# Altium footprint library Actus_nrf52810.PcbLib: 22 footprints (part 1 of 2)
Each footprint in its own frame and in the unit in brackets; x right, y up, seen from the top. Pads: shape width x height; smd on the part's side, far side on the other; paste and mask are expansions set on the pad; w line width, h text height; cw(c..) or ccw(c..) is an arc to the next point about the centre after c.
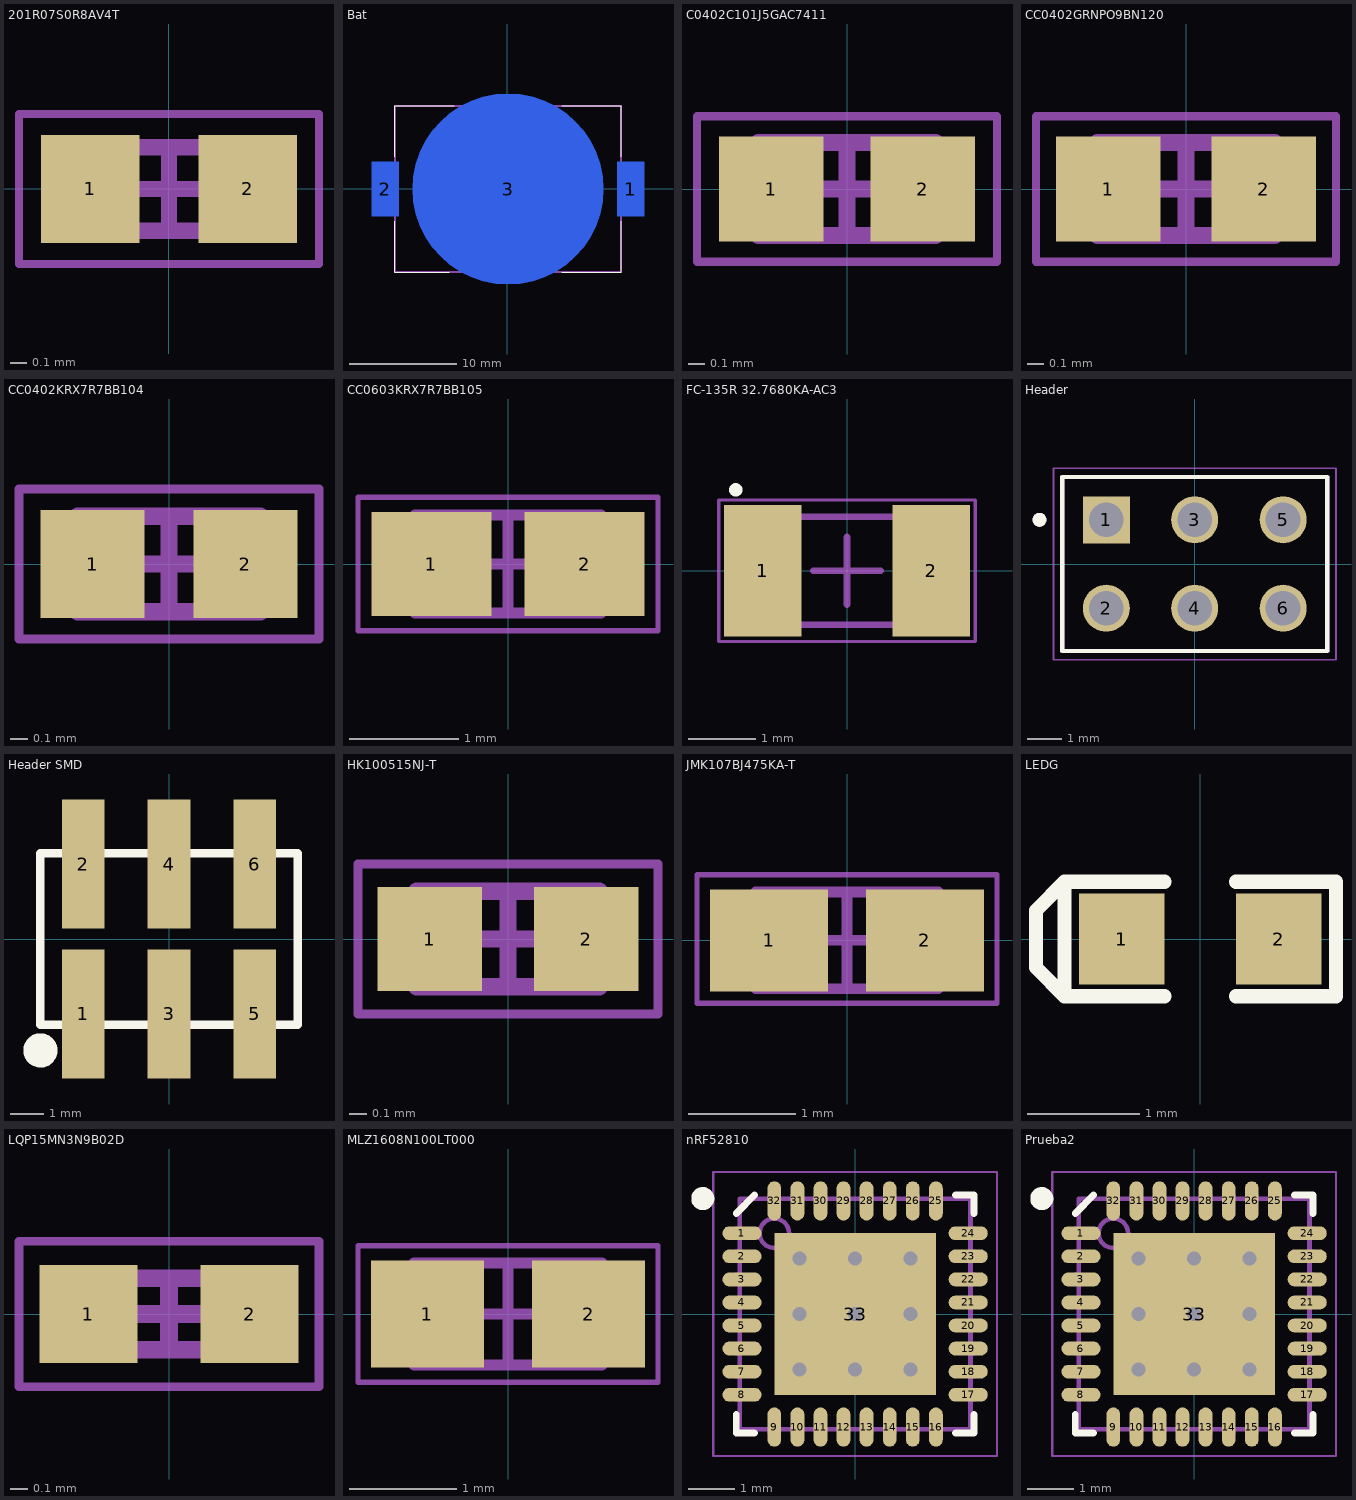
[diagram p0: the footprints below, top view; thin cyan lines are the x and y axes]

## 201R07S0R8AV4T [mm] "C3, 0.8pF, 0402, Johanson Dielectrics (Dimensiones no especificadas en datasheet, medidas tomadas de Mouser)"
height 0.64
pads (2):
  rect 0.6x0.66 smd: 1(-0.48,0) 2(0.48,0)
Mechanical 13:
  lines w0.1: -0.51,-0.255 0.51,-0.255 0.51,0.255 -0.51,0.255 -0.51,-0.255
Mechanical 15:
  lines w0.05: -0.914,-0.457 0.914,-0.457 0.914,0.457 -0.914,0.457 -0.914,-0.457
  lines w0.1: -0.255,0 0.255,0 ; 0,-0.255 0,0.255
3D body: height 0.64, standoff 0, extent 0.26,-0.255 0.51,0.255
3D body: height 0.64, standoff 0, extent -0.51,-0.255 -0.26,0.255
3D body: height 0.64, standoff 0, extent -0.26,-0.255 0.26,0.255

## Bat [mm]
pads (3):
  rect 2.5x5.1 smd far side: 1(11.501,-0.025) 2(-11.399,-0.025)
  round 17.8 smd far side mask+0.102: 3(0.051,-0.025)
Top Overlay:
  lines w0.1: -10.499,-3.025 -10.499,-7.775 -5.449,-7.775 ; -10.499,2.975 -10.499,7.725 -4.949,7.725 ; 5.051,-7.775 10.601,-7.775 10.601,-3.025 ; 5.051,7.725 10.601,7.725 10.601,2.975
Mechanical 13:
  lines w0.2: -10.499,-7.775 10.601,-7.775 10.601,7.725 -10.499,7.725 -10.499,-7.775
3D body "Coin Retainer.STEP": height 4.08, standoff 0.01, extent -11.519,-7.792 11.722,8.687
3D body: height 0.35, standoff -16.13, extent 2.794,-9.017 2.794,-9.017
3D body: height 2.9, standoff -2.9, extent 0.051,-0.025 0.051,-0.025

## C0402C101J5GAC7411 [mm] "C7: 100 pF, 0402, KEMET"
height 0.55
pads (2):
  rect 0.62x0.62 smd: 1(-0.45,0) 2(0.45,0)
Mechanical 13:
  lines w0.1: -0.525,-0.275 -0.525,0.275 0.525,0.275 0.525,-0.275 -0.525,-0.275
Mechanical 15:
  lines w0.05: -0.889,-0.432 -0.889,0.432 0.889,0.432 0.889,-0.432 -0.889,-0.432
  lines w0.1: -0.275,0 0.275,0 ; 0,-0.275 0,0.275
3D body: height 0.55, standoff 0, extent -0.225,-0.275 0.225,0.275
3D body: height 0.55, standoff 0, extent -0.525,-0.275 -0.225,0.275
3D body: height 0.55, standoff 0, extent 0.225,-0.275 0.525,0.275

## CC0402GRNPO9BN120 [mm] "C1, C2, C11, C12: 12pF, 0402, Yageo"
height 0.55
pads (2):
  rect 0.62x0.62 smd: 1(-0.46,0) 2(0.46,0)
Mechanical 13:
  lines w0.1: -0.525,-0.275 0.525,-0.275 0.525,0.275 -0.525,0.275 -0.525,-0.275
Mechanical 15:
  lines w0.05: -0.889,-0.432 -0.889,-0.229 -0.889,0.229 -0.889,0.432 0.889,0.432 0.889,-0.432 -0.889,-0.432
  lines w0.1: -0.275,0 0.275,0 ; 0,-0.275 0,0.275
3D body: height 0.55, standoff 0, extent 0.275,-0.275 0.525,0.275
3D body: height 0.55, standoff 0, extent -0.525,-0.275 -0.275,0.275
3D body: height 0.55, standoff 0, extent -0.275,-0.275 0.275,0.275

## CC0402KRX7R7BB104 [mm] "C4, C5, C8: 100nF (0.1uF), 0402, Yageo"
height 0.55
pads (2):
  rect 0.6x0.62 smd: 1(-0.44,0) 2(0.44,0)
Mechanical 13:
  lines w0.1: -0.525,-0.275 -0.525,0.275 0.525,0.275 0.525,-0.275 -0.525,-0.275
Mechanical 15:
  lines w0.05: -0.864,-0.432 -0.864,0.432 0.864,0.432 0.864,-0.432 -0.864,-0.432
  lines w0.1: -0.275,0 0.275,0 ; 0,-0.275 0,0.275
3D body: height 0.55, standoff 0, extent -0.275,-0.275 0.275,0.275
3D body: height 0.55, standoff 0, extent -0.525,-0.275 -0.275,0.275
3D body: height 0.55, standoff 0, extent 0.275,-0.275 0.525,0.275

## CC0603KRX7R7BB105 [mm] "C10: 1.0uF, 0603, Yageo"
height 0.9
pads (2):
  rect 1.1x0.95 smd: 1(-0.7,0) 2(0.7,0)
Mechanical 13:
  lines w0.1: -0.85,-0.45 -0.85,0.45 0.85,0.45 0.85,-0.45 -0.85,-0.45
Mechanical 15:
  lines w0.05: -1.372,-0.61 -1.372,0.61 1.372,0.61 1.372,-0.61 -1.372,-0.61
  lines w0.1: -0.45,0 0.45,0 ; 0,-0.45 0,0.45
3D body: height 0.9, standoff 0, extent -0.45,-0.45 0.45,0.45
3D body: height 0.9, standoff 0, extent -0.85,-0.45 -0.45,0.45
3D body: height 0.9, standoff 0, extent 0.45,-0.45 0.85,0.45

## FC-135R 32.7680KA-AC3 [mm] "X2: 32.7680KHZ, XTAL_3215, EPSON"
height 0.9
pads (2):
  rect 1.15x1.95 smd: 1(-1.25,0) 2(1.25,0)
Top Overlay:
  circle w0.1: c-1.65,1.2 r0.05
Mechanical 13:
  lines w0.1: -1.65,-0.8 1.65,-0.8 1.65,0.8 -1.65,0.8 -1.65,-0.8
Mechanical 15:
  lines w0.05: -1.9,-1.05 1.9,-1.05 1.9,1.05 -1.9,1.05 -1.9,-1.05
  lines w0.1: -0.5,0 0.5,0 ; 0,-0.5 0,0.5
3D body: height 0.9, standoff 0, extent -1.65,-0.8 1.65,0.8

## Header [mm]
pads (6):
  rect 1.35x1.35 hole 1: 1(-2.54,1.27)
  round 1.35 hole 1: 2(-2.54,-1.27) 3(0,1.27) 4(0,-1.27) 5(2.54,1.27) 6(2.54,-1.27)
Top Overlay:
  circle w0.2: c-4.46,1.27 r0.1
  lines w0.127: -3.81,-2.5 -3.81,2.5 3.81,2.5 3.81,-2.5 -3.81,-2.5
Mechanical 4:
  circle w0.2: c-4.46,1.27 r0.1
  circle w0.2: c-4.46,1.27 r0.1
  lines w0.127: -3.81,-2.5 -3.81,2.5 ; -3.81,-2.5 3.81,-2.5 ; -3.81,-2.5 3.81,-2.5 ; -3.81,-2.5 -3.81,2.5 ; -3.81,-2.5 3.81,-2.5 ; -3.81,-2.5 3.81,-2.5 ; -3.81,2.5 3.81,2.5 ; -3.81,2.5 3.81,2.5 ; 3.81,-2.5 3.81,2.5 ; 3.81,-2.5 3.81,2.5
Mechanical 16:
  lines w0.05: -4.06,-2.75 -4.06,2.75 4.06,2.75 4.06,-2.75 -4.06,-2.75
3D body: height 0.35, standoff -16.13, extent 2.54,1.27 2.54,1.27
3D body "CON6_2X3_P100UM_HDR.step": height 9.5, standoff -5.08, extent -3.81,-2.54 3.81,2.54

## Header SMD [mil]
pads (6):
  rect 50x150 smd: 1(-100,-87.5) 2(-100,87.5) 3(0,-87.5) 4(0,87.5) 5(100,-87.5) 6(100,87.5)
Top Overlay:
  circle w20: c-150,-130 r10
  lines w10: -150,-100 -150,100 150,100 150,-100 -150,-100
3D body "pin_header_a-sl254-dg-g06mp1.stp": height 382.03, standoff -1.57, extent -149.99,-147.63 150.01,147.64

## HK100515NJ-T [mm] "L3: 15nH, 0402, Taiyo Yuden"
height 0.55
pads (2):
  rect 0.6x0.6 smd: 1(-0.45,0) 2(0.45,0)
Mechanical 13:
  lines w0.1: -0.525,-0.275 0.525,-0.275 0.525,0.275 -0.525,0.275 -0.525,-0.275
Mechanical 15:
  lines w0.05: -0.864,-0.432 0.864,-0.432 0.864,0.432 -0.864,0.432 -0.864,-0.432
  lines w0.1: -0.275,0 0.275,0 ; 0,-0.275 0,0.275
3D body: height 0.55, standoff 0, extent 0.275,-0.275 0.525,0.275
3D body: height 0.55, standoff 0, extent -0.525,-0.275 -0.275,0.275
3D body: height 0.55, standoff 0, extent -0.275,-0.275 0.275,0.275

## JMK107BJ475KA-T [mm] "C9: 4.7uF, 0603, Taiyo Yuden"
height 0.9
pads (2):
  rect 1.1x0.95 smd: 1(-0.725,0) 2(0.725,0)
Mechanical 13:
  lines w0.1: -0.85,-0.45 0.85,-0.45 0.85,0.45 -0.85,0.45 -0.85,-0.45
Mechanical 15:
  lines w0.05: -1.397,-0.584 1.397,-0.584 1.397,0.61 -1.397,0.61 -1.397,-0.584
  lines w0.1: -0.45,0 0.45,0 ; 0,-0.45 0,0.45
3D body: height 0.9, standoff 0, extent 0.37,-0.45 0.85,0.45
3D body: height 0.9, standoff 0, extent -0.85,-0.45 -0.37,0.45
3D body: height 0.9, standoff 0, extent -0.37,-0.45 0.37,0.45

## LEDG [mil]
pads (2):
  rect 30x32 smd: 1(-27.5,0) 2(27.5,0)
Top Overlay:
  lines w5: -12.5,-20 -47.5,-20 ; -12.5,20 -47.5,20 ; 12.5,-20 47.5,-20 47.5,20 12.5,20 ; -47.5,-20 -57.5,-10 -57.5,10 -47.5,20 ; -47.5,-20 -47.5,20
3D body "User Library-led_0603_green.step": height 23.62, standoff 0, extent -31.63,-15.75 32.15,15.75

## LQP15MN3N9B02D [mm] "L1: 3.9 nH, 0402 (1005 metric), Murata Electronics"
height 0.45
pads (2):
  rect 0.55x0.55 smd: 1(-0.45,0) 2(0.45,0)
Mechanical 13:
  lines w0.1: -0.55,-0.2 -0.55,0.2 0.55,0.2 0.55,-0.2 -0.55,-0.2
Mechanical 15:
  lines w0.05: -0.838,-0.406 0.838,-0.406 0.838,0.406 0.483,0.406 -0.437,0.406 -0.838,0.406 -0.838,-0.406
  lines w0.1: -0.2,0 0.2,0 ; 0,-0.2 0,0.2
3D body: height 0.45, standoff 0, extent -0.3,-0.2 0.3,0.2
3D body: height 0.45, standoff 0, extent -0.55,-0.2 -0.3,0.2
3D body: height 0.45, standoff 0, extent 0.3,-0.2 0.55,0.2

## MLZ1608N100LT000 [mm] "L2: 10 uH, 0603 (1608 metric), TDK"
height 0.95
pads (2):
  rect 1.05x1 smd: 1(-0.75,0) 2(0.75,0)
Mechanical 13:
  lines w0.1: -0.875,-0.475 0.875,-0.475 0.875,0.475 -0.875,0.475 -0.875,-0.475
Mechanical 15:
  lines w0.05: -1.397,-0.635 1.397,-0.635 1.397,0.635 0.75,0.635 -0.75,0.635 -1.397,0.635 -1.397,-0.635
  lines w0.1: -0.475,0 0.475,0 ; 0,-0.475 0,0.475
3D body: height 0.95, standoff 0, extent 0.575,-0.475 0.875,0.475
3D body: height 0.95, standoff 0, extent -0.875,-0.475 -0.575,0.475
3D body: height 0.95, standoff 0, extent -0.575,-0.475 0.575,0.475

## nRF52810 [mm] "QFN, 32-Leads, Body 5.00x5.00mm, Pitch 0.50mm, Thermal Pad 3.50x3.50mm, IPC Medium Density"
height 0.9
pads (33):
  oval 0.85x0.3 smd mask+0.076: 1(-2.45,1.75) 2(-2.45,1.25) 3(-2.45,0.75) 4(-2.45,0.25) 5(-2.45,-0.25) 6(-2.45,-0.75) 7(-2.45,-1.25) 8(-2.45,-1.75) 17(2.45,-1.75) 18(2.45,-1.25) 19(2.45,-0.75) 20(2.45,-0.25) 21(2.45,0.25) 22(2.45,0.75) 23(2.45,1.25) 24(2.45,1.75)
  oval 0.3x0.85 smd mask+0.076: 9(-1.75,-2.45) 10(-1.25,-2.45) 11(-0.75,-2.45) 12(-0.25,-2.45) 13(0.25,-2.45) 14(0.75,-2.45) 15(1.25,-2.45) 16(1.75,-2.45) 25(1.75,2.45) 26(1.25,2.45) 27(0.75,2.45) 28(0.25,2.45) 29(-0.25,2.45) 30(-0.75,2.45) 31(-1.25,2.45) 32(-1.75,2.45)
  rect 3.5x3.5 smd: 33(0,0)
via 0,0 diameter 0.61 hole 0.305
via 0,1.2 diameter 0.61 hole 0.305
via -1.2,1.2 diameter 0.61 hole 0.305
via -1.2,0 diameter 0.61 hole 0.305
via -1.2,-1.2 diameter 0.61 hole 0.305
via 0,-1.2 diameter 0.61 hole 0.305
via 1.2,-1.2 diameter 0.61 hole 0.305
via 1.2,0 diameter 0.61 hole 0.305
via 1.2,1.2 diameter 0.61 hole 0.305
Top Overlay:
  circle w0.25: c-3.3,2.5 r0.125
  lines w0.15: -2.575,-2.175 -2.575,-2.575 -2.175,-2.575 ; -2.575,2.175 -2.175,2.575 ; 2.175,-2.575 2.575,-2.575 2.575,-2.175 ; 2.175,2.575 2.575,2.575 2.575,2.175
Mechanical 7:
  circle w0.1: c-1.75,1.75 r0.32
  lines w0.1: -2.5,-1.845 -2.571,-1.845 cw(c-2.571,-1.75) -2.571,-1.655 -2.5,-1.655 ; -2.5,-1.345 -2.571,-1.345 cw(c-2.571,-1.25) -2.571,-1.155 -2.5,-1.155 ; -2.5,-0.845 -2.571,-0.845 cw(c-2.571,-0.75) -2.571,-0.655 -2.5,-0.655 ; -2.5,-0.345 -2.571,-0.345 cw(c-2.571,-0.25) -2.571,-0.155 -2.5,-0.155 ; -2.5,0.155 -2.571,0.155 cw(c-2.571,0.25) -2.571,0.345 -2.5,0.345 ; -2.5,0.655 -2.571,0.655 cw(c-2.571,0.75) -2.571,0.845 -2.5,0.845 ; -2.5,1.155 -2.571,1.155 cw(c-2.571,1.25) -2.571,1.345 -2.5,1.345 ; -2.5,1.655 -2.571,1.655 cw(c-2.571,1.75) -2.571,1.845 -2.5,1.845 ; -1.845,-2.5 -1.845,-2.571 ccw(c-1.75,-2.571) -1.655,-2.571 -1.655,-2.5 ; -1.845,2.5 -1.845,2.571 cw(c-1.75,2.571) -1.655,2.571 -1.655,2.5 ; -1.345,-2.5 -1.345,-2.571 ccw(c-1.25,-2.571) -1.155,-2.571 -1.155,-2.5 ; -1.345,2.5 -1.345,2.571 cw(c-1.25,2.571) -1.155,2.571 -1.155,2.5 ; -0.845,-2.5 -0.845,-2.571 ccw(c-0.75,-2.571) -0.655,-2.571 -0.655,-2.5 ; -0.845,2.5 -0.845,2.571 cw(c-0.75,2.571) -0.655,2.571 -0.655,2.5 ; -0.345,-2.5 -0.345,-2.571 ccw(c-0.25,-2.571) -0.155,-2.571 -0.155,-2.5 ; -0.345,2.5 -0.345,2.571 cw(c-0.25,2.571) -0.155,2.571 -0.155,2.5 ; 0.155,-2.5 0.155,-2.571 ccw(c0.25,-2.571) 0.345,-2.571 0.345,-2.5 ; 0.155,2.5 0.155,2.571 cw(c0.25,2.571) 0.345,2.571 0.345,2.5 ; 0.655,-2.5 0.655,-2.571 ccw(c0.75,-2.571) 0.845,-2.571 0.845,-2.5 ; 0.655,2.5 0.655,2.571 cw(c0.75,2.571) 0.845,2.571 0.845,2.5 ; 1.155,-2.5 1.155,-2.571 ccw(c1.25,-2.571) 1.345,-2.571 1.345,-2.5 ; 1.155,2.5 1.155,2.571 cw(c1.25,2.571) 1.345,2.571 1.345,2.5 ; 1.655,-2.5 1.655,-2.571 ccw(c1.75,-2.571) 1.845,-2.571 1.845,-2.5 ; 1.655,2.5 1.655,2.571 cw(c1.75,2.571) 1.845,2.571 1.845,2.5 ; 2.5,-1.845 2.571,-1.845 ccw(c2.571,-1.75) 2.571,-1.655 2.5,-1.655 ; 2.5,-1.345 2.571,-1.345 ccw(c2.571,-1.25) 2.571,-1.155 2.5,-1.155 ; 2.5,-0.845 2.571,-0.845 ccw(c2.571,-0.75) 2.571,-0.655 2.5,-0.655 ; 2.5,-0.345 2.571,-0.345 ccw(c2.571,-0.25) 2.571,-0.155 2.5,-0.155 ; 2.5,0.155 2.571,0.155 ccw(c2.571,0.25) 2.571,0.345 2.5,0.345 ; 2.5,0.655 2.571,0.655 ccw(c2.571,0.75) 2.571,0.845 2.5,0.845 ; 2.5,1.155 2.571,1.155 ccw(c2.571,1.25) 2.571,1.345 2.5,1.345 ; 2.5,1.655 2.571,1.655 ccw(c2.571,1.75) 2.571,1.845 2.5,1.845 ; -2.5,-2.5 -2.5,2.5 2.5,2.5 2.5,-2.5 -2.5,-2.5
  text ".Designator" at -0.879,-0.131 h0.38
Mechanical 15:
  lines w0.05: -3.075,-3.075 3.075,-3.075 3.075,3.075 -3.075,3.075 -3.075,-3.075
  lines w0.1: -0.5,0 0.5,0 ; 0,-0.5 0,0.5
3D body "QFN50P500X500X90_HS-33N.step": height 0.9, standoff 0, extent -2.501,-2.501 2.501,2.501

## Prueba2 [mm]
pads (33):
  oval 0.85x0.3 smd mask+0.076: 1(-2.45,1.75) 2(-2.45,1.25) 3(-2.45,0.75) 4(-2.45,0.25) 5(-2.45,-0.25) 6(-2.45,-0.75) 7(-2.45,-1.25) 8(-2.45,-1.75) 17(2.45,-1.75) 18(2.45,-1.25) 19(2.45,-0.75) 20(2.45,-0.25) 21(2.45,0.25) 22(2.45,0.75) 23(2.45,1.25) 24(2.45,1.75)
  oval 0.3x0.85 smd mask+0.076: 9(-1.75,-2.45) 10(-1.25,-2.45) 11(-0.75,-2.45) 12(-0.25,-2.45) 13(0.25,-2.45) 14(0.75,-2.45) 15(1.25,-2.45) 16(1.75,-2.45) 25(1.75,2.45) 26(1.25,2.45) 27(0.75,2.45) 28(0.25,2.45) 29(-0.25,2.45) 30(-0.75,2.45) 31(-1.25,2.45) 32(-1.75,2.45)
  rect 3.5x3.5 smd: 33(0,0)
via 0,0 diameter 0.61 hole 0.305
via 0,1.2 diameter 0.61 hole 0.305
via -1.2,1.2 diameter 0.61 hole 0.305
via -1.2,0 diameter 0.61 hole 0.305
via -1.2,-1.2 diameter 0.61 hole 0.305
via 0,-1.2 diameter 0.61 hole 0.305
via 1.2,-1.2 diameter 0.61 hole 0.305
via 1.2,0 diameter 0.61 hole 0.305
via 1.2,1.2 diameter 0.61 hole 0.305
Top Overlay:
  circle w0.25: c-3.3,2.5 r0.125
  lines w0.15: -2.575,-2.175 -2.575,-2.575 -2.175,-2.575 ; -2.575,2.175 -2.175,2.575 ; 2.175,-2.575 2.575,-2.575 2.575,-2.175 ; 2.175,2.575 2.575,2.575 2.575,2.175
Mechanical 7:
  circle w0.1: c-1.75,1.75 r0.32
  lines w0.1: -2.5,-1.845 -2.571,-1.845 cw(c-2.571,-1.75) -2.571,-1.655 -2.5,-1.655 ; -2.5,-1.345 -2.571,-1.345 cw(c-2.571,-1.25) -2.571,-1.155 -2.5,-1.155 ; -2.5,-0.845 -2.571,-0.845 cw(c-2.571,-0.75) -2.571,-0.655 -2.5,-0.655 ; -2.5,-0.345 -2.571,-0.345 cw(c-2.571,-0.25) -2.571,-0.155 -2.5,-0.155 ; -2.5,0.155 -2.571,0.155 cw(c-2.571,0.25) -2.571,0.345 -2.5,0.345 ; -2.5,0.655 -2.571,0.655 cw(c-2.571,0.75) -2.571,0.845 -2.5,0.845 ; -2.5,1.155 -2.571,1.155 cw(c-2.571,1.25) -2.571,1.345 -2.5,1.345 ; -2.5,1.655 -2.571,1.655 cw(c-2.571,1.75) -2.571,1.845 -2.5,1.845 ; -1.845,-2.5 -1.845,-2.571 ccw(c-1.75,-2.571) -1.655,-2.571 -1.655,-2.5 ; -1.845,2.5 -1.845,2.571 cw(c-1.75,2.571) -1.655,2.571 -1.655,2.5 ; -1.345,-2.5 -1.345,-2.571 ccw(c-1.25,-2.571) -1.155,-2.571 -1.155,-2.5 ; -1.345,2.5 -1.345,2.571 cw(c-1.25,2.571) -1.155,2.571 -1.155,2.5 ; -0.845,-2.5 -0.845,-2.571 ccw(c-0.75,-2.571) -0.655,-2.571 -0.655,-2.5 ; -0.845,2.5 -0.845,2.571 cw(c-0.75,2.571) -0.655,2.571 -0.655,2.5 ; -0.345,-2.5 -0.345,-2.571 ccw(c-0.25,-2.571) -0.155,-2.571 -0.155,-2.5 ; -0.345,2.5 -0.345,2.571 cw(c-0.25,2.571) -0.155,2.571 -0.155,2.5 ; 0.155,-2.5 0.155,-2.571 ccw(c0.25,-2.571) 0.345,-2.571 0.345,-2.5 ; 0.155,2.5 0.155,2.571 cw(c0.25,2.571) 0.345,2.571 0.345,2.5 ; 0.655,-2.5 0.655,-2.571 ccw(c0.75,-2.571) 0.845,-2.571 0.845,-2.5 ; 0.655,2.5 0.655,2.571 cw(c0.75,2.571) 0.845,2.571 0.845,2.5 ; 1.155,-2.5 1.155,-2.571 ccw(c1.25,-2.571) 1.345,-2.571 1.345,-2.5 ; 1.155,2.5 1.155,2.571 cw(c1.25,2.571) 1.345,2.571 1.345,2.5 ; 1.655,-2.5 1.655,-2.571 ccw(c1.75,-2.571) 1.845,-2.571 1.845,-2.5 ; 1.655,2.5 1.655,2.571 cw(c1.75,2.571) 1.845,2.571 1.845,2.5 ; 2.5,-1.845 2.571,-1.845 ccw(c2.571,-1.75) 2.571,-1.655 2.5,-1.655 ; 2.5,-1.345 2.571,-1.345 ccw(c2.571,-1.25) 2.571,-1.155 2.5,-1.155 ; 2.5,-0.845 2.571,-0.845 ccw(c2.571,-0.75) 2.571,-0.655 2.5,-0.655 ; 2.5,-0.345 2.571,-0.345 ccw(c2.571,-0.25) 2.571,-0.155 2.5,-0.155 ; 2.5,0.155 2.571,0.155 ccw(c2.571,0.25) 2.571,0.345 2.5,0.345 ; 2.5,0.655 2.571,0.655 ccw(c2.571,0.75) 2.571,0.845 2.5,0.845 ; 2.5,1.155 2.571,1.155 ccw(c2.571,1.25) 2.571,1.345 2.5,1.345 ; 2.5,1.655 2.571,1.655 ccw(c2.571,1.75) 2.571,1.845 2.5,1.845 ; -2.5,-2.5 -2.5,2.5 2.5,2.5 2.5,-2.5 -2.5,-2.5
  text ".Designator" at -0.879,-0.131 h0.38
Mechanical 15:
  lines w0.05: -3.075,-3.075 3.075,-3.075 3.075,3.075 -3.075,3.075 -3.075,-3.075
  lines w0.1: -0.5,0 0.5,0 ; 0,-0.5 0,0.5
3D body "QFN50P500X500X90_HS-33N.step": height 0.9, standoff 0, extent -2.501,-2.501 2.501,2.501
